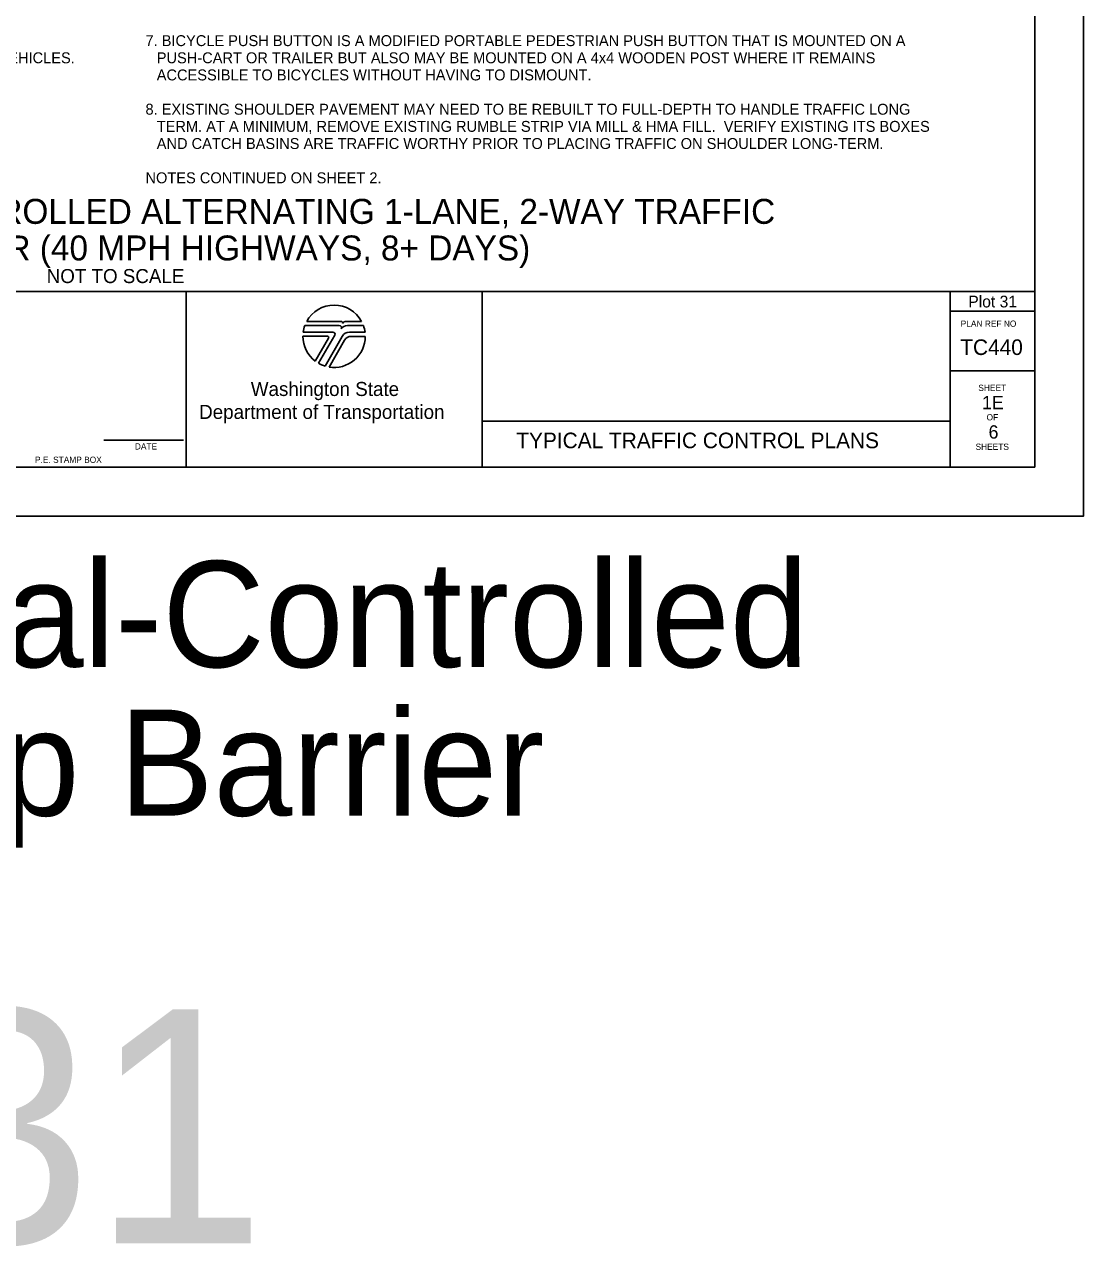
# Model space of a CAD drawing. Extents: x 99982 to 100176, y 99905 to 100011.
# Drawn here: x 100009.27 to 100016.06, y 99905.01 to 99912.84 of the extents above; entities that cross this region are included whole.
import ezdxf

# ---------------------------------------------------------------- set-up
doc = ezdxf.new("R2010")
doc.units = 0
for name, color, linetype in [('SH_DE_DetailHeading1Text', 7, 'Continuous'), ('SH_GI_GeneralNotesBodyText', 7, 'Continuous'), ('SH_GI_PlotLimits', 7, 'Continuous'), ('SH_GI_SheetBorder', 7, 'Continuous'), ('SH_GI_SheetLocationText', 7, 'Continuous'), ('SH_GI_SheetTextInCells', 7, 'Continuous'), ('SH_GI_TitleBlockText', 7, 'Continuous'), ('SH_GI_WSDOTLogo', 7, 'Continuous')]:
    doc.layers.add(name, color=color, linetype=linetype)

msp = doc.modelspace()

# ---------------------------------------------------------------- linework, layer by layer
at = {"layer": 'SH_GI_PlotLimits'}
msp.add_lwpolyline([(99999.0625, 99909.6875), (100016.0625, 99909.6875), (100016.0625, 99920.6875), (99999.0625, 99920.6875)], close=True, dxfattribs=at)
at = {"layer": 'SH_GI_SheetBorder'}
for p, q in [((100015.75, 99920.375), (100015.75, 99910)), ((100000, 99911.1259), (100015.75, 99911.1259)), ((100010.3089, 99911.1259), (100010.3089, 99910)), ((100012.2055, 99911.1259), (100012.2055, 99910)), ((100015.2079, 99911.1259), (100015.2079, 99910)), ((100015.2079, 99911.0008), (100015.75, 99911.0008)), ((100015.2079, 99910.6176), (100015.75, 99910.6176)), ((100012.2055, 99910.2955), (100015.2079, 99910.2955)), ((100009.7797, 99910.1733), (100010.2914, 99910.1733)), ((100000, 99910), (100015.75, 99910))]:
    msp.add_line(p, q, dxfattribs=at)
at = {"layer": 'SH_GI_WSDOTLogo'}
for p, q in [((100011.2894, 99910.9094), (100011.0697, 99910.9094)), ((100011.303, 99910.9354), (100011.0815, 99910.9354)), ((100011.433, 99910.9354), (100011.3351, 99910.9354)), ((100011.343, 99910.9094), (100011.3429, 99910.9094)), ((100011.4448, 99910.9094), (100011.343, 99910.9094)), ((100011.0572, 99910.84), (100011.2148, 99910.84)), ((100011.059, 99910.8661), (100011.2496, 99910.8661)), ((100011.222, 99910.8277), (100011.1364, 99910.6807)), ((100011.261, 99910.8464), (100011.1567, 99910.6672)), ((100011.1989, 99910.6487), (100011.3089, 99910.839)), ((100011.2244, 99910.6428), (100011.3242, 99910.8156)), ((100011.3558, 99910.8661), (100011.4555, 99910.8661)), ((100011.3655, 99910.8394), (100011.4572, 99910.8394))]:
    msp.add_line(p, q, dxfattribs=at)
for centre, radius, start, end in [((100011.2572, 99910.84), 0.2, 28.47865, 151.53204), ((100011.2572, 99910.84), 0.2, 159.69598, 172.50569), ((100011.2894, 99910.8946), 0.0148, 327.8418, 89.99855), ((100011.3429, 99910.861), 0.0484, 89.99529, 147.82376), ((100011.303, 99910.9263), 0.00903, 329.87418, 90.00328), ((100011.3352, 99910.9066), 0.0287, 90.00721, 148.16763), ((100011.2572, 99910.84), 0.2, 7.49431, 20.29406), ((100011.2572, 99910.84), 0.2, 179.99864, 232.84327), ((100011.2149, 99910.8318), 0.0082, 329.74356, 90), ((100011.2572, 99910.84), 0.2, 260.54554, 359.80857), ((100011.2497, 99910.853), 0.0131, 329.76834, 90), ((100011.3558, 99910.8119), 0.0542, 90, 149.99738), ((100011.3654, 99910.7918), 0.0476, 90, 150.05432), ((100011.2572, 99910.84), 0.2, 239.79292, 253.0448)]:
    msp.add_arc(centre, radius, start, end, dxfattribs=at)

# ---------------------------------------------------------------- texts
at = {"layer": 'SH_DE_DetailHeading1Text'}
for s, height, p in [('ADVANCED TEMPORARY SIGNAL-CONTROLLED ALTERNATING 1-LANE, 2-WAY TRAFFIC', 0.16, (100004.9788, 99911.5606)), ('25 WZSL + TEMP BARRIER (40 MPH HIGHWAYS, 8+ DAYS)', 0.16, (100006.57, 99911.3259)), ('NOT TO SCALE', 0.09, (100009.4141, 99911.1809))]:
    msp.add_text(s, height=height, rotation=360, dxfattribs=at).set_placement(p)
at = {"layer": 'SH_GI_GeneralNotesBodyText'}
for s, p in [('7. BICYCLE PUSH BUTTON IS A MODIFIED PORTABLE PEDESTRIAN PUSH BUTTON THAT IS MOUNTED ON A ', (100010.0475, 99912.6998)), (':  (1) DEFAULT TIMING PLAN DESIGNED ONLY FOR VEHICLES. ', (100006.7909, 99912.5899)), ('PUSH-CART OR TRAILER BUT ALSO MAY BE MOUNTED ON A 4x4 WOODEN POST WHERE IT REMAINS ', (100010.1197, 99912.5899)), ('ACCESSIBLE TO BICYCLES WITHOUT HAVING TO DISMOUNT.', (100010.1197, 99912.48)), ('8. EXISTING SHOULDER PAVEMENT MAY NEED TO BE REBUILT TO FULL-DEPTH TO HANDLE TRAFFIC LONG ', (100010.0475, 99912.2602)), ('TERM. AT A MINIMUM, REMOVE EXISTING RUMBLE STRIP VIA MILL & HMA FILL.  VERIFY EXISTING ITS BOXES ', (100010.1197, 99912.1503)), ('AND CATCH BASINS ARE TRAFFIC WORTHY PRIOR TO PLACING TRAFFIC ON SHOULDER LONG-TERM.', (100010.1197, 99912.0404)), ('NOTES CONTINUED ON SHEET 2.', (100010.0475, 99911.8206))]:
    msp.add_text(s, height=0.07, rotation=360, dxfattribs=at).set_placement(p)
at = {"layer": 'SH_GI_SheetBorder'}
msp.add_text('PLAN REF NO', height=0.040032, dxfattribs=at).set_placement((100015.2747, 99910.9008))
at = {"layer": 'SH_GI_SheetLocationText'}
for s, height, p in [('Plot 31', 0.075, (100015.3235, 99911.025)), (' Temp Signal-Controlled', 0.68, (100004.4951, 99908.7191)), ('Alt Traffic w/ Temp Barrier', 0.68, (100002.0459, 99907.7671)), ('Plot 31', 1.5, (100004.5756, 99905.0267))]:
    msp.add_text(s, height=height, dxfattribs=at).set_placement(p)
at = {"layer": 'SH_GI_SheetTextInCells'}
for s, height, p in [('Washington State', 0.090072, (100010.7229, 99910.4571)), ('SHEET', 0.04003, (100015.3877, 99910.4896)), ('Department of Transportation', 0.090072, (100010.3916, 99910.3101)), ('OF', 0.04003, (100015.4406, 99910.3008)), ('DATE', 0.04003, (100009.9794, 99910.1141)), ('SHEETS', 0.04003, (100015.3698, 99910.112)), ('P.E. STAMP BOX', 0.040032, (100009.339, 99910.0286))]:
    msp.add_text(s, height=height, dxfattribs=at).set_placement(p)
at = {"layer": 'SH_GI_TitleBlockText'}
for s, height, p in [('TC440', 0.1, (100015.2718, 99910.72)), ('1E', 0.085, (100015.4116, 99910.3723)), ('6', 0.085, (100015.4534, 99910.1843)), ('TYPICAL TRAFFIC CONTROL PLANS', 0.1, (100012.4251, 99910.1224))]:
    msp.add_text(s, height=height, dxfattribs=at).set_placement(p)

doc.saveas('drawing.dxf')
